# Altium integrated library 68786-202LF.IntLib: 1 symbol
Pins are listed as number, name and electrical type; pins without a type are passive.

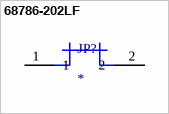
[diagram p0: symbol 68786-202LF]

## 68786-202LF
designator JP?
Low Profile Jumper , Single Row, 2 Positions, 2.54mm (0.100in) Pitch; MF: FCI; MP: 68786-202LF
footprint FCI_68786-202LF
pins: 1, 2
